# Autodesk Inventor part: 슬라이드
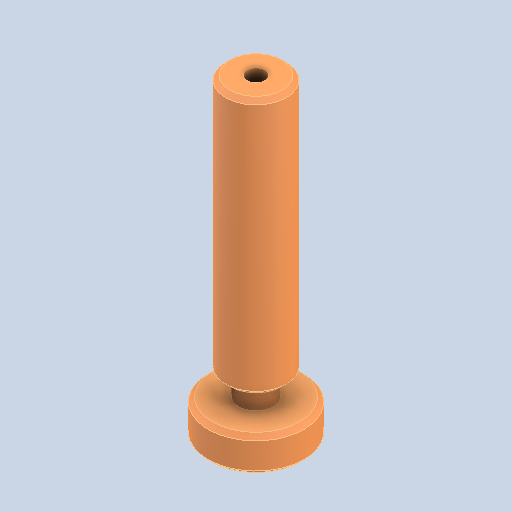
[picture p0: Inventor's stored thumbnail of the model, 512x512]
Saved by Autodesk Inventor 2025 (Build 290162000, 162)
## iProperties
Created: 2025-08
Part Number: 슬라이드
Material: 강철, 연강
Document SubType Name: Modeling
Designer: infra028
Density: 7.86 g/cm^3
Appearance: 기본값
Author: jhkim
Sending System: Autodesk Inventor 2026
Preprocessor: ST-DEVELOPER v20.1
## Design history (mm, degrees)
feature "솔리드1"
node "솔리드2"
